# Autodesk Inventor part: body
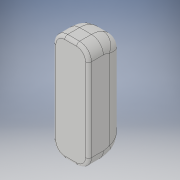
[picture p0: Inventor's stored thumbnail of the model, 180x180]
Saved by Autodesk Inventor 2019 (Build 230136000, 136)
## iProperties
Created: 2020-08
Part Number: body
Material: 一般
Document SubType Name: Modeling
Designer: kikut
Density: 1 g/cm^3
Appearance: 既定
Author: kikut
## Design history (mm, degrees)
sketch "スケッチ1"
  geometry: L1 (-0.06, -0.18)-(0.06, -0.18); L2 (0.06, -0.18)-(0.06, 0.18); L3 (0.06, 0.18)-(-0.06, 0.18); L4 (-0.06, 0.18)-(-0.06, -0.18); L5 (-0.06, -0.18)-(0.06, 0.18); L6 (0.06, -0.18)-(-0.06, 0.18); 1 further point
  constraints: 12 end point, 2 midpoint, 2 parallel, 1 horizontal, 1 perpendicular
  dimensions: "d0" = 0.36 distance of L1.end L2.end; "d1" = 0.12 distance of L2.end L3.end
extrude "押し出し1" new body sketch "スケッチ1" distance "d2" = 0.06; taper "d4" = 0 deg; dims "d3" = 0.07, "d5" = 0
fillet "フィレット2" dims "d7" = 0.08
sketch "スケッチ2"
  geometry: L1 (0.12, -0.05)-(0.12, -0.13) reference; L2 (0.12, -0.07)-(0.14, -0.07); L3 (0.14, -0.07)-(0.14, -0.17); L4 (0.14, -0.17)-(-0.02, -0.17); L5 (-0.02, -0.17)-(-0.02, -0.07); L6 (-0.02, -0.07)-(0, -0.07); L7 (0, 0)-(0.12, 0) reference; A1 r 0.06 centre (0.06, -0.07) between (0, -0.07) and (0.12, -0.07); 1 further point
  constraints: 10 end point, 4 perpendicular, 2 point on circle, 2 point on line, 1 centre point, 1 horizontal
  dimensions: "d8" = 0.06 radius of A1; "d9" = 0.02 distance of L5.end L6.end; "d10" = 0.02 distance of L2.start L2.end; "d11" = 0.16 distance of L3.end L4.end; "d12" = 0.1 distance of L2.end L3.end; "d13" = 0.13 dimension on A1 L7
extrude "押し出し2" cut sketch "スケッチ2" extent not by distance; stored distance "d14" = 0.06; taper "d15" = 0 deg
fillet "フィレット3" dims "d16" = 0.04
fillet "フィレット4" dims "d17" = 0.01
node "ソリッド1"
